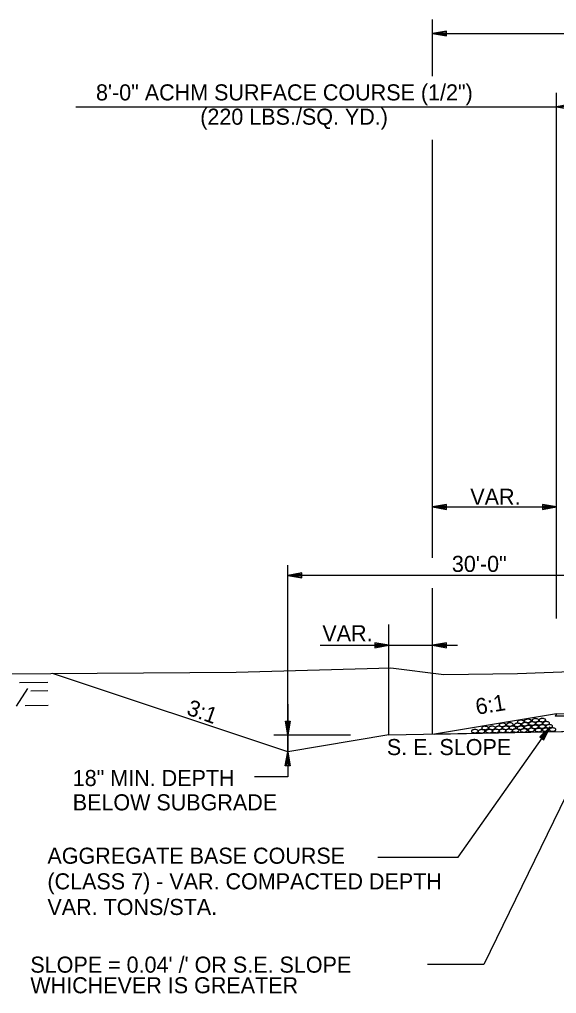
# Model space of a CAD drawing. Extents: x 1734743 to 1735935, y 759845 to 763831.
# Drawn here: x 1735642.8 to 1735682.8, y 760128.5 to 760201.2 of the extents above; entities that cross this region are included whole.
import ezdxf

# ---------------------------------------------------------------- set-up
doc = ezdxf.new("R2010")
doc.units = 0
for name, color, linetype in [('1', 7, 'Continuous'), ('10', 7, 'Continuous'), ('11', 7, 'Continuous'), ('19', 7, 'Continuous'), ('9', 7, 'Continuous'), ('Level 1', 7, 'Continuous'), ('Level 9', 7, 'Continuous'), ('R_Prop Surface', 7, 'Continuous')]:
    doc.layers.add(name, color=color, linetype=linetype)

# ---------------------------------------------------------------- blocks, each defined once
blk = doc.blocks.new('ROCKS')
at = {"layer": '1'}
blk.add_spline([(0.013, 0.06), (0.053, 0.053), (0.107, 0.033), (0.133, 0.013), (0.133, -0.007), (0.12, -0.033), (0.107, -0.04), (0.073, -0.053), (0.033, -0.067), (0.013, -0.067), (-0.02, -0.06), (-0.06, -0.053), (-0.087, -0.047), (-0.113, -0.02), (-0.113, -0.007), (-0.107, 0.02), (-0.087, 0.033), (-0.067, 0.047), (-0.033, 0.053), (-0.02, 0.06), (0.013, 0.06)], degree=3, dxfattribs=at)

msp = doc.modelspace()

# ---------------------------------------------------------------- linework, layer by layer
at = {"layer": '11'}
msp.add_lwpolyline([(1735627.813, 760152.266), (1735658.939, 760152.469), (1735670.487, 760152.809), (1735674.441, 760152.307), (1735679.922, 760152.367), (1735689.862, 760152.763), (1735696.495, 760152.722), (1735705.488, 760152.844), (1735712.606, 760153.149)], dxfattribs=at)
at = {"layer": '19'}
for p, q in [((1735673.577, 760196.963), (1735673.577, 760201.184)), ((1735674.628, 760200.321), (1735673.577, 760200.138)), ((1735673.577, 760200.138), (1735733.567, 760200.138)), ((1735673.577, 760200.138), (1735674.627, 760199.954)), ((1735674.628, 760200.225), (1735673.857, 760200.164)), ((1735673.857, 760200.112), (1735674.627, 760200.041)), ((1735674.627, 760199.954), (1735674.628, 760200.321)), ((1735682.837, 760166.512), (1735682.837, 760195.722)), ((1735683.887, 760194.86), (1735682.837, 760194.676)), ((1735646.98, 760194.676), (1735682.837, 760194.676)), ((1735682.837, 760194.676), (1735683.887, 760194.492)), ((1735690.837, 760194.676), (1735682.837, 760194.676)), ((1735673.577, 760161.006), (1735673.577, 760192.213)), ((1735674.628, 760164.996), (1735673.577, 760164.812)), ((1735673.577, 760164.812), (1735674.627, 760164.628)), ((1735674.628, 760164.9), (1735673.857, 760164.838)), ((1735673.857, 760164.786), (1735674.627, 760164.716)), ((1735674.627, 760164.628), (1735674.628, 760164.996)), ((1735681.787, 760164.996), (1735681.787, 760164.628)), ((1735682.837, 760164.812), (1735681.787, 760164.996)), ((1735682.557, 760164.838), (1735681.787, 760164.899)), ((1735681.787, 760164.628), (1735682.837, 760164.812)), ((1735681.787, 760164.716), (1735682.557, 760164.785)), ((1735663.842, 760159.884), (1735662.792, 760159.701)), ((1735662.792, 760159.701), (1735663.842, 760159.517)), ((1735663.842, 760159.788), (1735663.072, 760159.727)), ((1735663.072, 760159.674), (1735663.842, 760159.604)), ((1735663.842, 760159.517), (1735663.842, 760159.884)), ((1735673.577, 760147.855), (1735673.577, 760158.738)), ((1735670.332, 760147.79), (1735670.332, 760156.025)), ((1735665.219, 760154.488), (1735675.443, 760154.488)), ((1735669.282, 760154.672), (1735669.282, 760154.304)), ((1735670.332, 760154.488), (1735669.282, 760154.672)), ((1735670.052, 760154.514), (1735669.282, 760154.576)), ((1735669.282, 760154.304), (1735670.332, 760154.488)), ((1735669.282, 760154.392), (1735670.052, 760154.462)), ((1735674.627, 760154.672), (1735673.577, 760154.488)), ((1735673.577, 760154.488), (1735674.627, 760154.304)), ((1735674.627, 760154.575), (1735673.857, 760154.514)), ((1735673.857, 760154.462), (1735674.627, 760154.392)), ((1735674.627, 760154.304), (1735674.627, 760154.672)), ((1735662.792, 760146.533), (1735645.252, 760152.38)), ((1735642.563, 760149.945), (1735643.407, 760151.249)), ((1735642.787, 760151.701), (1735644.892, 760151.724)), ((1735643.633, 760151.086), (1735644.904, 760151.1)), ((1735643.208, 760150.002), (1735644.925, 760150.021)), ((1735662.792, 760146.533), (1735662.792, 760149.988)), ((1735682.834, 760149.373), (1735673.741, 760147.858)), ((1735682.75, 760149.205), (1735690.823, 760149.367)), ((1735682.834, 760149.373), (1735690.823, 760149.533)), ((1735662.61, 760148.83), (1735662.978, 760148.83)), ((1735662.794, 760147.78), (1735662.61, 760148.83)), ((1735662.768, 760148.06), (1735662.698, 760148.83)), ((1735662.978, 760148.83), (1735662.794, 760147.78)), ((1735662.882, 760148.83), (1735662.82, 760148.06)), ((1735675.493, 760138.674), (1735682.353, 760148.399)), ((1735682.353, 760148.399), (1735681.598, 760147.646)), ((1735681.899, 760147.438), (1735682.353, 760148.399)), ((1735670.332, 760147.79), (1735662.792, 760146.533)), ((1735670.332, 760147.79), (1735686.838, 760148.12)), ((1735673.741, 760147.858), (1735690.823, 760148.2)), ((1735681.598, 760147.646), (1735681.899, 760147.438)), ((1735682.175, 760148.183), (1735681.677, 760147.596)), ((1735681.828, 760147.488), (1735682.216, 760148.154)), ((1735662.609, 760145.483), (1735662.792, 760146.533)), ((1735662.696, 760145.483), (1735662.766, 760146.253)), ((1735662.792, 760146.533), (1735662.976, 760145.483)), ((1735662.819, 760146.253), (1735662.88, 760145.483)), ((1735662.976, 760145.483), (1735662.609, 760145.483)), ((1735669.509, 760138.674), (1735675.493, 760138.674))]:
    msp.add_line(p, q, dxfattribs=at)
for points in [[(1735662.792, 760150.08), (1735662.792, 760144.661), (1735660.299, 760144.661)], [(1735690.823, 760149.367), (1735682.75, 760149.205), (1735682.75, 760149.205), (1735682.834, 760149.373), (1735682.834, 760149.373), (1735682.834, 760149.373), (1735690.823, 760149.533), (1735690.823, 760149.533), (1735690.823, 760149.533), (1735690.823, 760149.367), (1735690.823, 760149.367), (1735690.823, 760149.367)]]:
    msp.add_lwpolyline(points, dxfattribs=at)
at = {"layer": '9'}
for p, q in [((1735682.837, 760156.476), (1735682.837, 760166.512)), ((1735673.577, 760164.812), (1735682.837, 760164.812)), ((1735662.792, 760149.552), (1735662.792, 760160.467)), ((1735692.837, 760159.701), (1735662.796, 760159.701)), ((1735686.55, 760149.448), (1735677.423, 760130.652)), ((1735677.423, 760130.652), (1735673.206, 760130.652))]:
    msp.add_line(p, q, dxfattribs=at)
at = {"layer": 'Level 9'}
msp.add_line((1735661.753, 760147.79), (1735667.473, 760147.79), dxfattribs=at)
at = {"layer": 'R_Prop Surface'}
msp.add_line((1735682.834, 760149.373), (1735682.75, 760149.205), dxfattribs=at)

# ---------------------------------------------------------------- block references
at = {"layer": 'Level 1', "xscale": 2.011654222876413, "yscale": 2.011654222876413, "rotation": 1.8263814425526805}
for p in [(1735681.76, 760148.908), (1735677.485, 760148.318), (1735678.011, 760148.328), (1735678.522, 760148.328), (1735678.788, 760148.551), (1735679.033, 760148.328), (1735679.342, 760148.575), (1735679.525, 760148.334), (1735679.916, 760148.548), (1735680.133, 760148.334), (1735680.145, 760148.779), (1735680.47, 760148.596), (1735680.673, 760148.851), (1735680.687, 760148.381), (1735681.002, 760148.655), (1735681.221, 760148.401), (1735681.242, 760148.89), (1735681.529, 760148.669), (1735681.752, 760148.426), (1735682.015, 760148.188), (1735682.046, 760148.668), (1735682.278, 760148.442), (1735682.528, 760148.197), (1735676.725, 760148.08), (1735677.23, 760148.068), (1735677.795, 760148.081), (1735678.294, 760148.095), (1735678.79, 760148.105), (1735679.287, 760148.113), (1735679.777, 760148.129), (1735680.385, 760148.129), (1735680.939, 760148.176), (1735681.479, 760148.164)]:
    msp.add_blockref('ROCKS', p, dxfattribs=at)

# ---------------------------------------------------------------- texts
at = {"layer": '10'}
for s, p in [('VAR.', (1735676.408, 760164.966)), ('30\'-0"', (1735675.034, 760159.958)), ('S. E. SLOPE', (1735670.181, 760146.289))]:
    msp.add_text(s, height=1.2, dxfattribs=at).set_placement(p)
for s, rotation, p in [('6:1', 9.45113, (1735676.902, 760149.291)), ('3:1', 340.49426, (1735655.172, 760149.338)), ('18" MIN. DEPTH', 360, (1735646.752, 760143.977)), ('BELOW SUBGRADE', 360, (1735646.752, 760142.165)), ("SLOPE = 0.04' /' OR S.E. SLOPE", 360, (1735643.591, 760130.052)), ('WHICHEVER IS GREATER', 360, (1735643.591, 760128.514))]:
    msp.add_text(s, height=1.2, rotation=rotation, dxfattribs=at).set_placement(p)
at = {"layer": '19'}
for s, p in [('8\'-0" ACHM SURFACE COURSE (1/2")', (1735648.485, 760195.143)), ('(220 LBS./SQ. YD.)', (1735656.262, 760193.33)), ('VAR.', (1735665.371, 760154.785))]:
    msp.add_text(s, height=1.2, dxfattribs=at).set_placement(p)
for s, p in [('AGGREGATE BASE COURSE', (1735644.863, 760138.181)), ('(CLASS 7) - VAR. COMPACTED DEPTH', (1735644.863, 760136.269)), ('VAR. TONS/STA.', (1735644.863, 760134.357))]:
    msp.add_text(s, height=1.2, rotation=360, dxfattribs=at).set_placement(p)

doc.saveas('drawing.dxf')
